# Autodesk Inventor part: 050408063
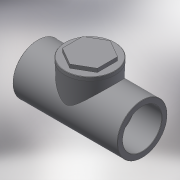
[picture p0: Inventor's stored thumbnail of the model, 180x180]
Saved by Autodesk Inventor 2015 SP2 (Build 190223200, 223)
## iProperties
Created: 2017-10
Part Number: 050408063
Material: Generic
Description: PLASSON CHECK VALVE T-CLAPPERALVE-CEMENT 63
Document SubType Name: Modeling
Designer: KIM
Density: 1 g/cm^3
Appearance: Default
Author: KIM
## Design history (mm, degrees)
derived "050408.ipt"
feature "Solid1::050408.ipt"
feature "Solid2::050408.ipt"
tag "TaggingFeature1"
body "Solid1"
other parameters: "d1" = 73, "d2" = 38, "d4" = 63, "d5" = 50.9904, "d7" = 0.56656, "d8" = 38, "d15" = 0, "d18" = 56.656, "d24" = 0.56656, "d37" = 51.1, "d38" = 6, "d39" = 0, "d41" = 73, "d42" = 6, "d43" = 69.35, "G_" = 56.656, "E_" = 73, "lt_" = 13, "l_" = 38, "d_" = 63
